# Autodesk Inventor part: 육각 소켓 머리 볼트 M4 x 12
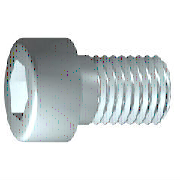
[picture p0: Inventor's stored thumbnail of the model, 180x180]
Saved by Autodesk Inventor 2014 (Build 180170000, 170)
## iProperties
IsCustomPart: 1
Created: 2012-02
Part Number: 육각 소켓 머리 볼트 M4 x 12
Material: 스테인리스강
Description: 6각 소켓 머리 캡 나사
Document SubType Name: Modeling
Standard: ISO 4762
Designer: mdu-01
Standard Revision: Fourth edition 2004-03-01
Standards Organization: ISO
Language: ko-KR
Size Designation: M4 x 12
Categories: <MemberInstance><Categories><Category DisplayName="조임쇠" InternalName="e4da775c-781d-43d5-af7c-5136215cf5a6" Mnemonic="FSTN"><Category DisplayName="볼트" InternalN
Density: 8.08 g/cm^3
Mass: 2.2972 g
Surface Area: 3.30853 cm^2
Volume: 0.284306 cm^3
Appearance: 반광택
Author: mdu-01
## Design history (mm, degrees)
sketch "스케치1"
  geometry: L1 (-1, 0)-(12, 0); L2 (12, 0)-(12, 2); L3 (12, 2)-(1.75, 2); L4 (1.75, 2)-(1.32, 2); L5 (1.32, 2)-(0, 2); L6 (0, 2)-(0, 3.5); L7 (0, 3.5)-(-4, 3.5); L8 (-4, 3.5)-(-4, 1.732); L9 (-4, 1.732)-(-2, 1.732); L10 (-2, 1.732)-(-1, 0); L11 (-7.2, 0)-(15.2, 0) reference; L12 (0, -0.7)-(0, 4.2) reference; L13 (1.75, 2)-(0, 2)
  constraints: 22 end point, 6 parallel, 2 collinear, 2 perpendicular, 1 horizontal, 1 point on line
  dimensions: "d1" = 10.25 distance from line of L3.end L2 (= GEL); "d2" = 0.42952 distance of L4.end L3.end (computed from GAL); "d3" = 4 distance between parallel lines of L8 L6 (= KOH); "d4" = 2 distance of L8.end L9.end (= INTI); "d5" = 60 deg angle of L10 L1; "d6" = 4 diameter of L3 L1 (= GD); "d7" = 4 diameter of L5 L1 (= BDM); "d8" = 3.4641 diameter of L9 L1 (= 1.1547 x SW); "d9" = 7 diameter of L7 L1 (= KOD); "d26" = 12 distance between parallel lines of L12 L2 (= NLG)
revolve "본체" sketch "스케치1" stored, may be unused: angle "d10" = 90 deg
sketch "스케치2"
  geometry: L1 (0, -4.9)-(0, 4.9) reference; L2 (-4.9, 0)-(4.9, 0) reference; L3 (1.732, 0)-(0.866, -1.5); L4 (0.866, -1.5)-(-0.866, -1.5); L5 (-0.866, -1.5)-(-1.732, 0); L6 (-1.732, 0)-(-0.866, 1.5); L7 (-0.866, 1.5)-(0.866, 1.5); L8 (0.866, 1.5)-(1.732, 0); 2 further points
  constraints: 12 end point, 1 coincident, 1 horizontal alignment, 1 point on line, 12 other
extrude "슬롯" join sketch "스케치2" stored distance "d11" = 10; taper "d12" = 0 deg
workplane "Work Plane1"
fillet "Fillet2" dims "d30" = 0.1 (= R)
body "Solid1"
fillet "모깎기1" dims "d17" = 0.4 (= RR)
feature "스레드" dims "d13" = 10.25 (= GEL), "d14" = 0
chamfer "모따기1" distance "d15" = 0.42941 (= -0.5 x SPD + 0.5 x GD); stored, may be unused: second distance "d16" = 0.42941 (= GUL), angle "d27" = 45 deg
other parameters: "GD" = 4 [user parameter; used in 2 equation terms], "NLG" = 12 [user parameter; used in 1 equation term], "GEL" = 10.25 [user parameter; used in 2 equation terms], "KOD" = 7 [user parameter; used in 1 equation term], "KOH" = 4 [user parameter; used in 1 equation term], "INTI" = 2 [user parameter; used in 1 equation term], "GAL" = 0.42941 (= 0.61345 x PTC) [user parameter; used in 1 equation term], "GUL" = 0.42941 (= 0.61345 x PTC) [user parameter; used in 1 equation term], "BDM" = 4 (= NND) [user parameter; used in 1 equation term], "SW" = 3 [user parameter; used in 2 equation terms], "RR" = 0.4 [user parameter; used in 1 equation term], "SPD" = 3.14117 (= NND - 1.2269 x PTC) [user parameter; used in 1 equation term], "d19" = 0, "d28" = 0, "d29" = 0, "R" = 0.1 [user parameter; used in 1 equation term], "TOA" = 30 deg [user parameter], "GD1" = 3.14117 (= THREADDIA - 1.2269 x PTC) [user parameter], "THREADDIA" = 4 [user parameter; used in 1 equation term], "FAWI" = 45 deg [user parameter], "TPU" = 14.28571 (computed from PTC) [user parameter], "PTC" = 0.7 [user parameter; used in 5 equation terms], "NND" = 4 [user parameter; used in 2 equation terms], "E0" = 3.465 (= 1.155 x SW) [user parameter]
